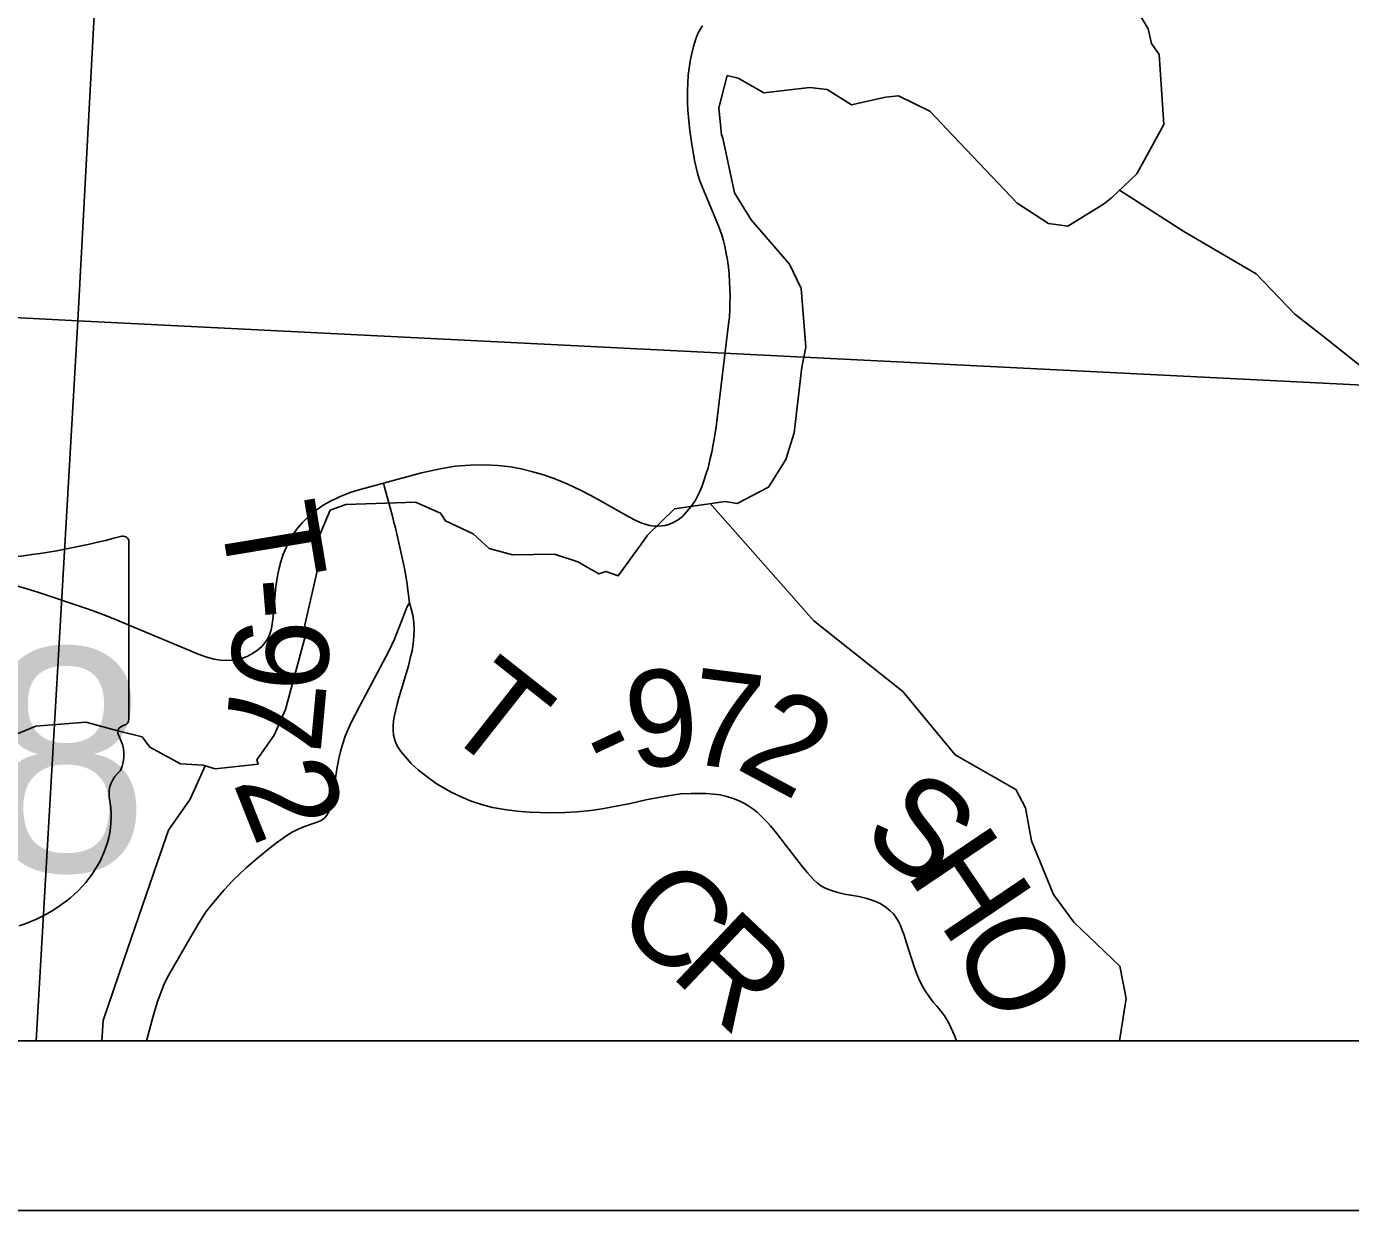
# Model space of a CAD drawing. Extents: x -2.1 to 31.9, y 6.3 to 28.3.
# Drawn here: x 1.171 to 1.952, y 20.344 to 21.042 of the extents above; entities that cross this region are included whole.
import ezdxf

# ---------------------------------------------------------------- set-up
doc = ezdxf.new("R2010")
doc.units = 0
for name, color, linetype in [('Default', 7, 'Continuous'), ('GM_X_Minor_River', 7, 'Continuous'), ('GM_X_Section', 7, 'Continuous'), ('GM_X_State_Route', 7, 'Continuous'), ('GM_X_State_Shield', 7, 'Continuous'), ('GM_X_Township_Road', 7, 'Continuous'), ('GM_X_Township_Road_Text', 7, 'Continuous'), ('SH_Cut_Line', 7, 'Continuous'), ('SH_Data', 7, 'Continuous')]:
    doc.layers.add(name, color=color, linetype=linetype)

msp = doc.modelspace()

# ---------------------------------------------------------------- linework, layer by layer
at = {"layer": 'Default'}
for points in [[(0.03444, 26.1105), (0.03444, 20.44396), (3.75329, 20.44396), (3.84891, 20.53885), (3.98943, 20.63262), (4.15995, 20.7203), (4.28946, 20.76624), (4.3023, 20.76577), (4.30914, 20.87135), (4.3751, 21.89793), (4.41684, 22.52383), (4.43833, 22.80674), (4.46511, 23.24053), (4.49006, 23.6442), (4.54731, 24.59544), (4.56672, 24.90844), (4.6032, 25.48157), (4.62861, 25.8765), (3.86248, 25.91583), (3.07625, 25.95547), (2.80342, 25.96832), (2.07568, 26.00469), (0.46414, 26.08833)], [(0.13259, 20.44396), (1.17686, 20.44396), (1.2015, 20.86872), (0.16057, 20.92297)], [(1.17686, 20.44396), (2.20346, 20.44396), (2.20563, 20.47903), (2.21242, 20.58684), (2.2269, 20.81748), (1.2015, 20.86872)]]:
    msp.add_lwpolyline(points, close=True, dxfattribs=at)
at = {"layer": 'GM_X_Minor_River'}
for points in [[(1.84209, 20.98446), (1.83931, 21.02586), (1.83477, 21.03231), (1.83287, 21.04105), (1.82076, 21.06116)], [(1.63081, 20.85315), (1.62813, 20.88773), (1.62131, 20.90215), (1.59861, 20.92832), (1.58877, 20.94426), (1.58193, 20.97654), (1.58117, 20.97844), (1.57965, 20.9944), (1.58454, 21.01342), (1.59097, 21.01191), (1.6061, 21.00321), (1.63331, 21.00632), (1.64352, 21.00521), (1.65789, 20.99612), (1.67792, 21.00074), (1.68548, 21.00151), (1.70402, 20.99244), (1.71801, 20.97766), (1.75547, 20.93823), (1.77401, 20.92611), (1.78535, 20.92463), (1.80651, 20.9376), (1.81104, 20.94103), (1.82614, 20.95552), (1.84209, 20.98446)], [(1.81602, 20.94581), (1.85389, 20.92137), (1.8966, 20.89647), (1.91931, 20.87259), (1.9363, 20.85952), (1.99646, 20.81167), (2.01444, 20.79402), (2.04124, 20.78026), (2.12457, 20.76091), (2.15946, 20.76474), (2.18726, 20.77184), (2.24024, 20.77396)], [(1.15624, 20.62127), (1.17664, 20.62968), (1.20613, 20.63203), (1.22579, 20.62676), (1.2394, 20.62337), (1.24394, 20.6173), (1.26209, 20.60746), (1.27533, 20.60674), (1.28251, 20.60447), (1.30784, 20.6072), (1.30708, 20.60986), (1.31727, 20.62432), (1.32406, 20.63954), (1.33611, 20.6848), (1.33535, 20.68936), (1.34326, 20.72358), (1.344, 20.74221), (1.35041, 20.75704), (1.35948, 20.76049), (1.40069, 20.76173), (1.41543, 20.75531), (1.41846, 20.75075), (1.43472, 20.74319), (1.44418, 20.73448), (1.45779, 20.73071), (1.48274, 20.73115), (1.49635, 20.72663), (1.50884, 20.71944), (1.51299, 20.72097), (1.52018, 20.71833), (1.53528, 20.73927), (1.53754, 20.74232), (1.55341, 20.75794), (1.58326, 20.7622), (1.59045, 20.76107), (1.60896, 20.77062), (1.61915, 20.78699), (1.62405, 20.80259), (1.62855, 20.84136), (1.63081, 20.85315)], [(1.57442, 20.76093), (1.63564, 20.69172), (1.68805, 20.65019), (1.71904, 20.61275), (1.75471, 20.59226), (1.76043, 20.58145), (1.764, 20.56197), (1.77702, 20.53042), (1.789, 20.51409), (1.81619, 20.48817), (1.81977, 20.46907), (1.81594, 20.44396)], [(1.27665, 20.60632), (1.26779, 20.58657), (1.25495, 20.5683), (1.24816, 20.54852), (1.22856, 20.49184), (1.2165, 20.45609), (1.21569, 20.44396)]]:
    msp.add_lwpolyline(points, dxfattribs=at)
at = {"layer": 'GM_X_Section'}
for points in [[(0.77277, 21.931), (1.25907, 21.91577), (1.26179, 21.91558), (1.25012, 21.72495), (1.22439, 21.29531), (1.2015, 20.86872), (0.16057, 20.92297), (0.22471, 21.95065)], [(2.25264, 21.24002), (2.2269, 20.81748), (1.2015, 20.86872), (1.22439, 21.29531)]]:
    msp.add_lwpolyline(points, close=True, dxfattribs=at)
at = {"layer": 'GM_X_State_Route'}
msp.add_lwpolyline([(1.16287, 20.71317), (1.17784, 20.7087), (1.20652, 20.6991), (1.21364, 20.69648), (1.22136, 20.69348), (1.27299, 20.67193), (1.2775, 20.67039), (1.28195, 20.66924), (1.2857, 20.66864), (1.28914, 20.66848), (1.29221, 20.66864), (1.29558, 20.6691), (1.29872, 20.66986), (1.30132, 20.67085), (1.30415, 20.67231), (1.30722, 20.67438), (1.3102, 20.67691), (1.31188, 20.67889), (1.31342, 20.68104), (1.31457, 20.68349), (1.31545, 20.68652), (1.3161, 20.68977), (1.31665, 20.69439), (1.31827, 20.71204), (1.31878, 20.71581), (1.31942, 20.71924), (1.32021, 20.72276), (1.32124, 20.72661), (1.3225, 20.73051), (1.32394, 20.73408), (1.32578, 20.73792), (1.32779, 20.74149), (1.33054, 20.74562), (1.33399, 20.74976), (1.33778, 20.75355), (1.34186, 20.75688), (1.34617, 20.75992), (1.35047, 20.76239), (1.35553, 20.7648), (1.35915, 20.7663), (1.36268, 20.76764), (1.36667, 20.76894), (1.38172, 20.77304), (1.40423, 20.77918), (1.41524, 20.78152), (1.42412, 20.78297), (1.433, 20.78366), (1.44165, 20.78389), (1.44916, 20.78351), (1.45674, 20.78259), (1.46302, 20.78145), (1.46904, 20.77997), (1.47555, 20.7781), (1.48254, 20.77565), (1.49055, 20.7724), (1.49839, 20.76874), (1.50399, 20.76576), (1.5098, 20.76256), (1.52654, 20.75309), (1.53067, 20.75097), (1.53423, 20.74942), (1.53665, 20.74867), (1.53894, 20.74804), (1.54164, 20.74764), (1.54365, 20.74758), (1.54589, 20.74775), (1.5479, 20.74804), (1.55014, 20.74867), (1.55272, 20.74971), (1.55557, 20.75139), (1.55808, 20.75342), (1.56074, 20.7562), (1.56333, 20.75932), (1.56573, 20.76302), (1.56793, 20.76721), (1.56948, 20.77091), (1.57078, 20.77435), (1.57201, 20.77803), (1.57323, 20.782), (1.57457, 20.78749), (1.57545, 20.79135), (1.5763, 20.79581), (1.57722, 20.80123), (1.57792, 20.80631), (1.58538, 20.86677), (1.58581, 20.87112), (1.58602, 20.8754), (1.58613, 20.87919), (1.58625, 20.8831), (1.58613, 20.88758), (1.5859, 20.89183), (1.58564, 20.89625), (1.58526, 20.90039), (1.5847, 20.90458), (1.58401, 20.90837), (1.58309, 20.91285), (1.58238, 20.916), (1.58138, 20.91945), (1.58047, 20.92212), (1.57943, 20.92484), (1.56996, 20.94736), (1.56844, 20.95132), (1.56721, 20.95507), (1.56614, 20.95921), (1.56525, 20.96334), (1.56438, 20.96825), (1.56343, 20.97416), (1.56251, 20.98097), (1.56189, 20.98671), (1.56139, 20.99305), (1.56116, 20.99742), (1.56108, 21.00086), (1.56116, 21.00462), (1.56131, 21.00921), (1.56158, 21.01353), (1.562, 21.01772), (1.56269, 21.02192), (1.56361, 21.02644), (1.56468, 21.03058), (1.56606, 21.03502), (1.56729, 21.03816), (1.56857, 21.04069), (1.57001, 21.04282)], dxfattribs=at)
at = {"layer": 'GM_X_State_Shield'}
for p, q in [((1.23153, 20.63371), (1.23153, 20.73839)), ((1.2315, 20.63373), (1.23153, 20.63371))]:
    msp.add_line(p, q, dxfattribs=at)
for centre, major_axis, start_param, end_param in [((1.11413, 21.00627), (0.34952, 0), 4.814394, 5.042369), ((1.22788, 20.73883), (0.00367, 0), 6.141152, 7.989035), ((1.22762, 20.6333), (0.00393, 0), 5.05454, 6.418171), ((1.23069, 20.62602), (0.00568, 0), 1.883978, 3.671073), ((1.19456, 20.61279), (0.03409, 0), 5.934695, 6.695948), ((1.24468, 20.5899), (0.0248, 0), 2.387724, 3.262537), ((1.13371, 20.57658), (0.08742, 0), 5.101752, 6.440018)]:
    msp.add_ellipse(centre, major_axis=major_axis, ratio=0.8, start_param=start_param, end_param=end_param, dxfattribs=at)
at = {"layer": 'GM_X_Township_Road'}
for points in [[(1.38172, 20.77304), (1.38238, 20.7706), (1.38726, 20.75268), (1.38797, 20.74989), (1.38878, 20.74668), (1.39393, 20.72367), (1.39476, 20.71954), (1.39549, 20.71469), (1.39704, 20.70237), (1.39815, 20.69892), (1.39906, 20.69516), (1.39962, 20.69103), (1.3998, 20.68682), (1.39967, 20.68267), (1.39925, 20.67827), (1.39863, 20.67414), (1.39781, 20.6705), (1.39645, 20.66531), (1.39212, 20.6508), (1.3908, 20.6463), (1.38978, 20.64259), (1.38881, 20.63847), (1.38798, 20.63421), (1.38753, 20.63049), (1.38742, 20.62776), (1.38778, 20.62434), (1.38872, 20.62077), (1.3901, 20.61772), (1.39202, 20.61463), (1.3945, 20.61167), (1.39821, 20.60768), (1.40241, 20.60369), (1.40756, 20.59978), (1.41293, 20.59592), (1.41719, 20.59331), (1.42172, 20.59077), (1.42755, 20.58792), (1.43349, 20.58547), (1.4396, 20.58341), (1.44599, 20.58176), (1.45322, 20.58045), (1.46071, 20.57949), (1.46793, 20.57894), (1.47425, 20.57867), (1.48051, 20.57853), (1.48876, 20.57874), (1.49598, 20.57915), (1.50409, 20.57997), (1.51083, 20.58094), (1.51895, 20.58238), (1.52741, 20.5841), (1.53662, 20.58616), (1.54404, 20.58767), (1.55078, 20.58884), (1.55711, 20.58967), (1.5633, 20.59001), (1.5675, 20.59004), (1.57209, 20.58994), (1.57668, 20.58952), (1.58039, 20.58906), (1.58431, 20.58824), (1.58808, 20.58705), (1.59153, 20.58566), (1.59463, 20.58411), (1.59725, 20.58256), (1.59968, 20.58097), (1.60221, 20.5789), (1.60421, 20.577), (1.60638, 20.57488), (1.60818, 20.57303), (1.61009, 20.57086), (1.61357, 20.56646), (1.62894, 20.54674), (1.63218, 20.54288), (1.63541, 20.53931), (1.63774, 20.53711), (1.6396, 20.53566), (1.64201, 20.53422), (1.64537, 20.53285), (1.64985, 20.53147), (1.65363, 20.53065), (1.65741, 20.52996), (1.66208, 20.52913), (1.66697, 20.52803), (1.67157, 20.52645), (1.67514, 20.5248), (1.67837, 20.52267), (1.68065, 20.52081), (1.68257, 20.51889), (1.68409, 20.5169), (1.68553, 20.51449), (1.68669, 20.51201), (1.68779, 20.5094), (1.68888, 20.50635), (1.69006, 20.50252), (1.69501, 20.48705), (1.69651, 20.48298), (1.69789, 20.47968), (1.69968, 20.47638), (1.70133, 20.47356), (1.70337, 20.47045), (1.70607, 20.46682), (1.7082, 20.46448), (1.71033, 20.46194), (1.71267, 20.45871), (1.71492, 20.45524), (1.71671, 20.45152), (1.71865, 20.44722), (1.71987, 20.44396)], [(1.24203, 20.44396), (1.24639, 20.46001), (1.24849, 20.46717), (1.25036, 20.47244), (1.25251, 20.47759), (1.25495, 20.48262), (1.26839, 20.50576), (1.27283, 20.51352), (1.27722, 20.5203), (1.28254, 20.5269), (1.28777, 20.53305), (1.29318, 20.53882), (1.30079, 20.54615), (1.30656, 20.55101), (1.31325, 20.5566), (1.31866, 20.56091), (1.32471, 20.56522), (1.32783, 20.56705), (1.3314, 20.56889), (1.33512, 20.57038), (1.34207, 20.57277), (1.34454, 20.57387), (1.34674, 20.57524), (1.3484, 20.57717), (1.34968, 20.57946), (1.35066, 20.58236), (1.35142, 20.5856), (1.35206, 20.58955), (1.3543, 20.60439), (1.35524, 20.60959), (1.35643, 20.61473), (1.35772, 20.6194), (1.35925, 20.62374), (1.36089, 20.62784), (1.36261, 20.6315), (1.36788, 20.64169), (1.38491, 20.67391), (1.38668, 20.67758), (1.38819, 20.68099), (1.39509, 20.69871), (1.39585, 20.70025), (1.39704, 20.70237)]]:
    msp.add_lwpolyline(points, dxfattribs=at)
at = {"layer": 'SH_Cut_Line'}
msp.add_lwpolyline([(0.03444, 27.24396), (0.03444, 20.44396), (3.75329, 20.44396)], dxfattribs=at)
at = {"layer": 'SH_Data'}
for p, q in [((0.03444, 20.44396), (6.83444, 20.44396)), ((-0.06556, 20.34396), (6.93444, 20.34396))]:
    msp.add_line(p, q, dxfattribs=at)

# ---------------------------------------------------------------- texts
at = {"layer": 'GM_X_State_Shield'}
msp.add_text('218', height=0.131836, dxfattribs=at).set_placement((0.94957, 20.54398))
at = {"layer": 'GM_X_Township_Road_Text'}
for s, rotation, p in [('T', 279.43239, (1.28489, 20.7563)), ('-', 274.76722, (1.2917, 20.71559)), ('9', 267.05325, (1.29361, 20.69436)), ('T', 321.69344, (1.41406, 20.62898)), ('9', 7.21939, (1.52852, 20.60375)), ('7', 352.65642, (1.55916, 20.60812)), ('7', 264.73654, (1.29186, 20.66001)), ('2', 331.78578, (1.58842, 20.60534)), ('-', 25.1589, (1.51209, 20.59522)), ('2', 291.70522, (1.29278, 20.59656)), ('S', 322.48486, (1.66211, 20.56294)), ('H', 304.01136, (1.68921, 20.54311)), ('C', 317.65451, (1.5156, 20.51453)), ('R', 316.55808, (1.54988, 20.48329)), ('O', 296.36956, (1.71617, 20.50339))]:
    msp.add_text(s, height=0.05682, rotation=rotation, dxfattribs=at).set_placement(p)

doc.saveas('drawing.dxf')
